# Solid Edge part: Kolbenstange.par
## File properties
Author: bmolnar
Last saved by: bmolnar
Revision: 78
Sűrűség: 0,000 kg/m^3
Pontosság: 0,990
Username: bmolnar
Dokumentum tartalom típus: 0
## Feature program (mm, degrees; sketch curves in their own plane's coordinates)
base feature "unnamed BaseFeature 1"
thread "unnamed Thread 1"
sketch for "unnamed Protrusion 1" plane through (0, 0, -44.25) normal (0, 0, -1) x-axis (0, -1, 0)
  circle centre (0, 0) radius 31.5
extrude "unnamed Protrusion 1" add finite 21.5 along -normal
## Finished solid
Body 1: solid body, 17 faces, 23 edges, 8 vertices.
  Faces by surface: plane 8, cylinder 4, torus 3, cone 2
  Edges by curve: circle 13, line 6, ellipse 2, intersection 2
Bounding box of the edges (mm; curved faces can reach further): 63.000 x 63.000 x 75.250, from (-31.5, -31.5, -44.25) to (31.5, 31.5, 31).
Cylindrical faces by radius (mm): R5 x1, R6 x1, R8 x1, R31.5 x1
Conical faces (half-angle, radius in mm at the cone's reference point): 20 deg R5.5 x1, 60 deg R5.6 x1
Toroidal faces (ring radius, tube radius in mm): R5.4 r0.4 x2, R6.3 r1.7 x1
Planar faces by outward normal: +x 1, +z 3, -x 1, -z 1, oblique 2
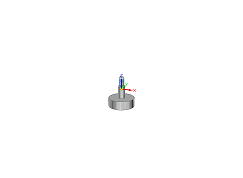
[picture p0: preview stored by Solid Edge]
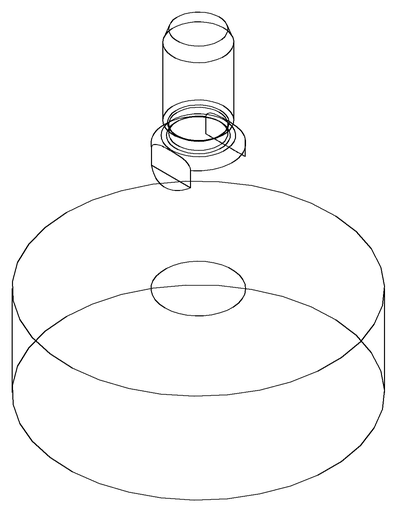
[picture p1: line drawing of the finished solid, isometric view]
